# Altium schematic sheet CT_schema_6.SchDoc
size 226 x 144 mm
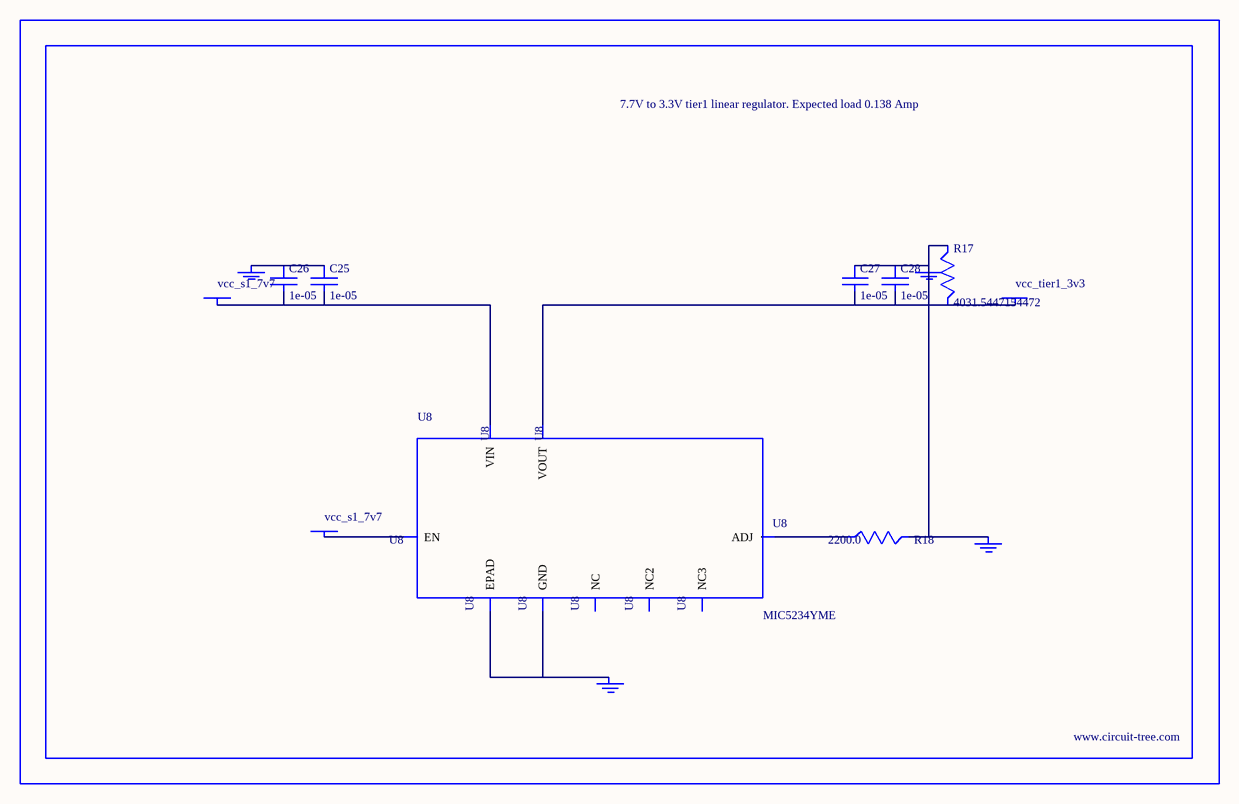
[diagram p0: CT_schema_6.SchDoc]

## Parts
BORDER5  (no value)
C25  1e-05  [C1210]
C26  1e-05  [C1210]
C27  1e-05  [C1210]
C28  1e-05  [C1210]
GND_INSTANCE_5_0  (no value)
GND_INSTANCE_5_1  (no value)
GND_INSTANCE_5_2  (no value)
GND_INSTANCE_5_3  (no value)
POWER_INSTANCE_5_0  vcc_tier1_3v3
POWER_INSTANCE_5_1  vcc_s1_7v7
POWER_INSTANCE_5_2  vcc_s1_7v7
R17  4031.5447154472  [R0603]
R18  2200.0  [R0603]
U8  MIC5234YME  [SOIC-8_EP]

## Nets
NetC25_1: C25.1 C26.1 GND_INSTANCE_5_3.0(GND)
NetC25_2: C25.2 C26.2 POWER_INSTANCE_5_2.0(PWR) U8.8(VIN)
NetC27_1: C27.1 C28.1 GND_INSTANCE_5_0.0(GND) GND_INSTANCE_5_1.0(GND) R17.1 R18.2
NetC27_2: C27.2 C28.2 POWER_INSTANCE_5_0.0(PWR) R17.2 U8.1(VOUT)
NetGND_INSTANCE_5_2_0: GND_INSTANCE_5_2.0(GND) U8.7(GND) U8.EPAD
NetPOWER_INSTANCE_5_1_0: POWER_INSTANCE_5_1.0(PWR) U8.5(EN)
NetR18_1: R18.1 U8.4(ADJ)

Not connected (* = marked no-connect by the designer): U8 2(NC) 3(NC2) 6(NC3)

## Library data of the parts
BORDER5 = BORDER_PAGE5
C25-C28 = C1210C106K5PACTU
GND_INSTANCE_5_0-GND_INSTANCE_5_3 = GND
POWER_INSTANCE_5_0-POWER_INSTANCE_5_2 = PWR
R17 = R17
R18 = RC0603JR-072K2L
